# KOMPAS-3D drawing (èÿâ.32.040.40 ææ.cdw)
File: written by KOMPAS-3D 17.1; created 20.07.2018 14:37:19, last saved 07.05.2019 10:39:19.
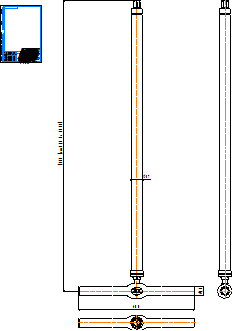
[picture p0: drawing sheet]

Sheet 1: A4, portrait

Title block, sheet 1: name: КШГ.32.040.40 СС; material: Внимание! Данный продукт является объектом авторского права ООО «Торговый Дом АДЛ». / Запрещается изменение, копирование, распространение / (в том числе путем копирования на другие сайты и ресурсы в Интернете) / или любое иное использование информации и объектов без предварительного / согласия правообладателя (ООО «Торговый Дом АДЛ»).; sheets: 1; organisation: ООО "Торговый дом АДЛ"; sheet format: A4; stored path: C:\Users\tra\Desktop\2д чертежи\Шаровые краны БИВАЛ\КШ_Бивал_серия_32\KOMPAS 2D\КШГ.32.040.40 СС.cdw

Views: Вид 1, Проекционный вид 2, Проекционный вид 3
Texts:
  kka
  adl
  (от 245 до 5000)
Dimensions and other numbers on the sheet: 600; 1500; 48; 57; 1:1; 1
